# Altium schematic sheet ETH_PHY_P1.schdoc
size 594 x 419 mm; Symbol: Drawing-Symbol_A4; @Project Name: FPGA_motors_V3_0_4; @Page Count: 1; @Update Date: 2025-12-23; @Create Date: 2025-12-23; @Schematic Name: ETH_PHY; @Page No: 1; @Page Name: P1; Company: EasyEDA.com; Version: V1.0; Page Size: A4; @Create Time: 13:22:03; @Update Time: 14:22:09; Border: 1; Width: 2338; Height: 1652; Region Start: 1; X Region Count: 6; Y Region Count: 4; Blade Width: 10; Title Block Position: 3; Device: Drawing-Symbol_A4
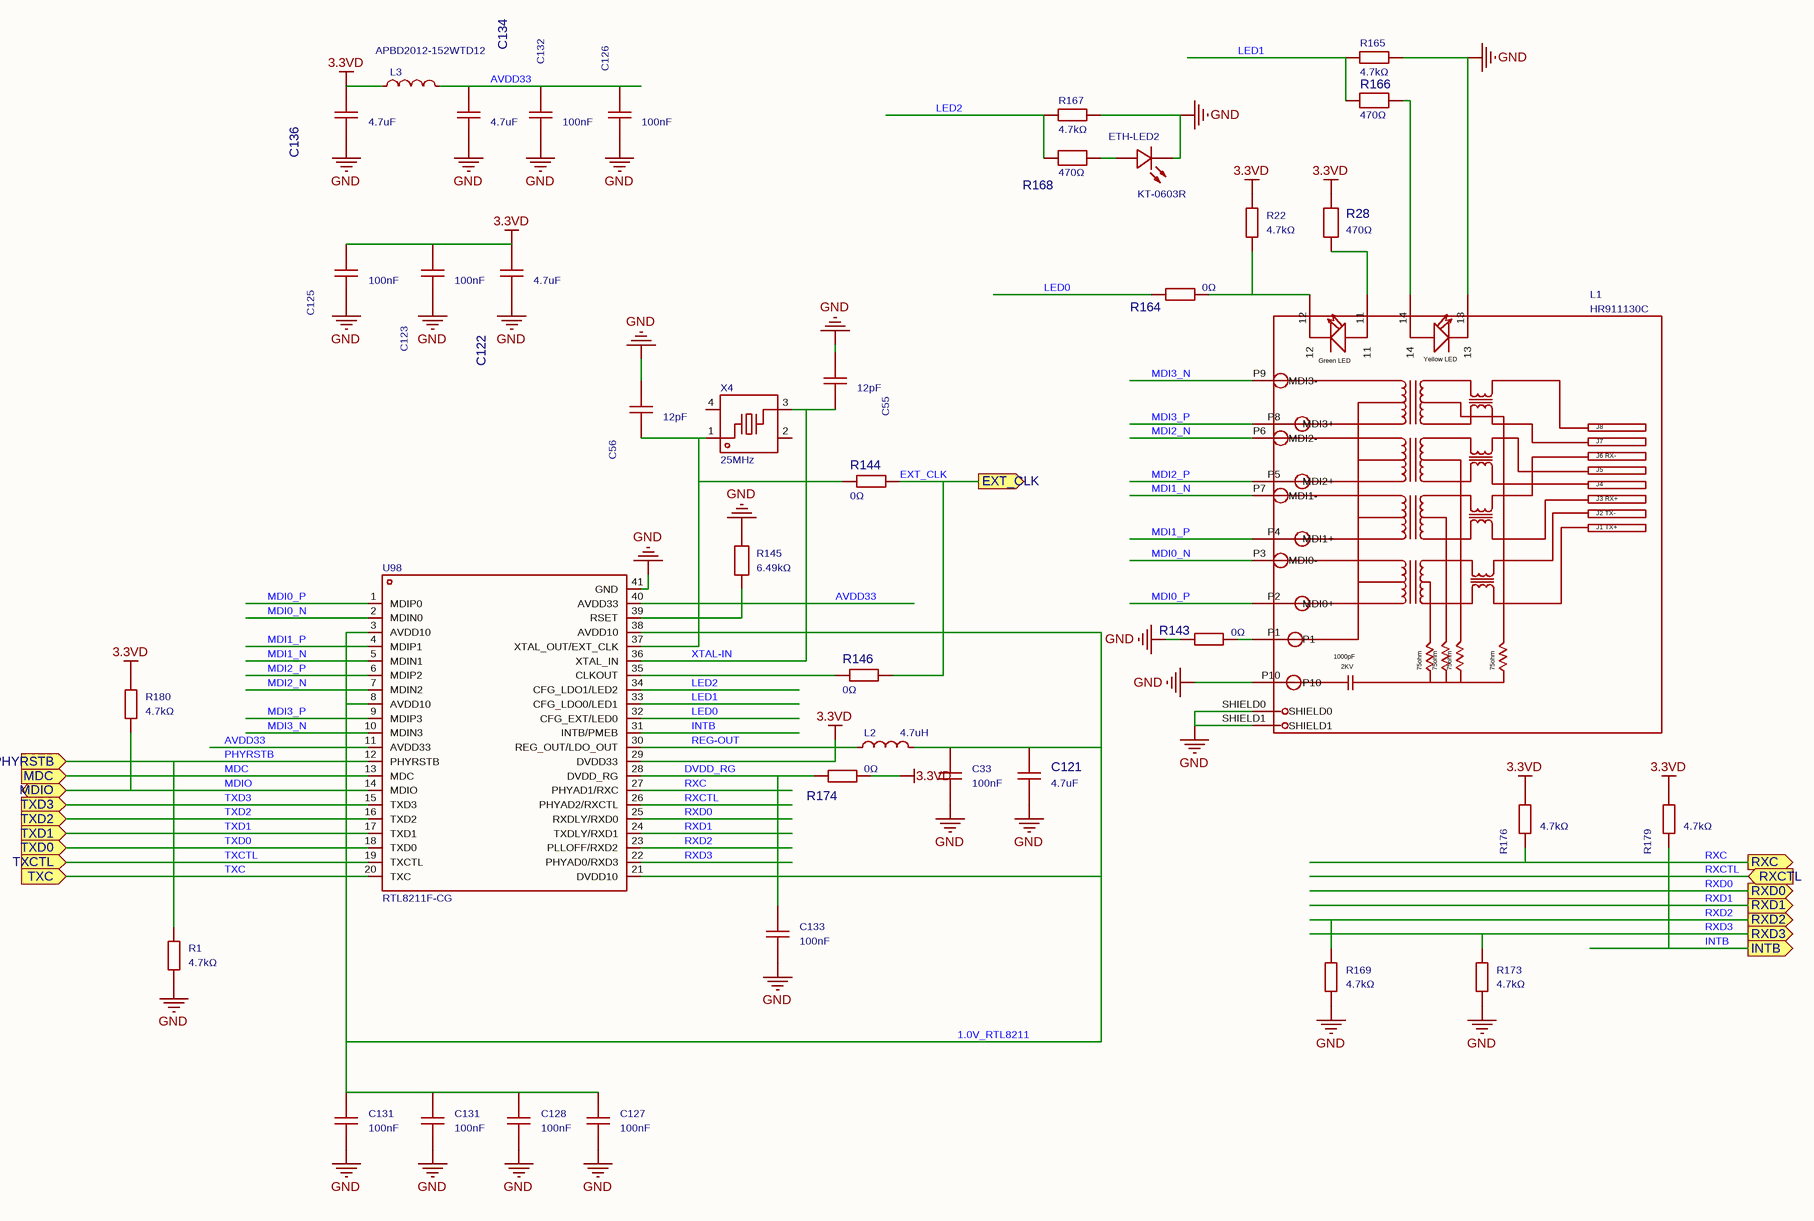
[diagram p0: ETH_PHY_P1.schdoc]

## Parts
(Parts that share a designator on the sheet are numbered #1, #2 ... from top to bottom, then left to right.)
C33  100nF  [C0402]
C55  12pF  [C0402]
C56  12pF  [C0402]
C121  4.7uF  [C0402]
C122  4.7uF  [C0402]
C123  100nF  [C0402]
C125  100nF  [C0402]
C126  100nF  [C0402]
C127  100nF  [C0402]
C128  100nF  [C0402]
C131#1  100nF  [C0402]
C131#2  100nF  [C0402]
C132  100nF  [C0402]
C133  100nF  [C0402]
C134  4.7uF  [C0402]
C136  4.7uF  [C0402]
ETH-LED2  KT-0603R  [LED0603-RD]
L1  HR911130C  [RJ45-TH_HR911130C]
L2  4.7uH  [IND-SMD_L7.8-W7.0_SUMIDA_CD73]
L3  APBD2012-152WTD12  [L0805]
R1  4.7kΩ  [R0402]
R22  4.7kΩ  [R0402]
R28  470Ω  [R0402]
R143  0Ω  [R0402]
R144  0Ω  [R0402]
R145  6.49kΩ  [R0402]
R146  0Ω  [R0402]
R164  0Ω  [R0402]
R165  4.7kΩ  [R0402]
R166  470Ω  [R0402]
R167  4.7kΩ  [R0402]
R168  470Ω  [R0402]
R169  4.7kΩ  [R0402]
R173  4.7kΩ  [R0402]
R174  0Ω  [R0402]
R176  4.7kΩ  [R0402]
R179  4.7kΩ  [R0402]
R180  4.7kΩ  [R0402]
U98  RTL8211F-CG  [WQFN-40_L5.0-W5.0-P0.4-BL-EP]
X4  25MHz  [CRYSTAL-SMD_4P-L5.0-W3.2-BL]

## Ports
EXT_CLK (out), INTB (out), MDC (in), MDIO (bidir), PHYRSTB (in), RXC (out), RXCTL (in), RXD0 (out), RXD1 (out), RXD2 (out), RXD3 (out), TXC (in), TXCTL (in), TXD0 (in), TXD1 (in), TXD2 (in), TXD3 (in)

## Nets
3.3VD: C122.1 C123.1 C125.1 C136.1 L3.1 R22.2 R28.2 R174.2 R176.1 R179.1 R180.1 U98.29(DVDD33)
GND: C33.2 C55.2 C56.2 C121.2 C122.2 C123.2 C125.2 C126.2 C127.2 C128.2 C131#1.2 C131#2.2 C132.2 C133.2 C134.2 C136.2 ETH-LED2.1(K) L1.13 L1.P10 L1.SHIELD0 L1.SHIELD1 R1.2 R143.1 R145.2 R165.1 R167.1 R169.2 R173.2 U98.41(GND)
1.0V_RTL8211: C33.1 C121.1 C127.1 C128.1 C131#1.1 C131#2.1 L2.2 U98.3(AVDD10) U98.8(AVDD10) U98.21(DVDD10) U98.38(AVDD10)
AVDD33: C126.1 C132.1 C134.1 L3.2 U98.11(AVDD33) U98.40(AVDD33)
DVDD_RG: C133.1 R174.1 U98.28(DVDD_RG)
EXT_CLK: R144.2 R146.2 ; port EXT_CLK
INTB: R179.2 U98.31(INTB/PMEB) ; port INTB
LED0: R164.1 U98.32(CFG_EXT/LED0)
LED1: R165.2 R166.2 U98.33(CFG_LDO0/LED1)
LED2: R167.2 R168.2 U98.34(CFG_LDO1/LED2)
MDC: U98.13(MDC) ; port MDC
MDI0_N: L1.P3(MDI0-) U98.2(MDIN0)
MDI0_P: L1.P2(MDI0+) U98.1(MDIP0)
MDI1_N: L1.P7(MDI1-) U98.5(MDIN1)
MDI1_P: L1.P4(MDI1+) U98.4(MDIP1)
MDI2_N: L1.P6(MDI2-) U98.7(MDIN2)
MDI2_P: L1.P5(MDI2+) U98.6(MDIP2)
MDI3_N: L1.P9(MDI3-) U98.10(MDIN3)
MDI3_P: L1.P8(MDI3+) U98.9(MDIP3)
MDIO: R180.2 U98.14(MDIO) ; port MDIO
PHYRSTB: R1.1 U98.12(PHYRSTB) ; port PHYRSTB
REG-OUT: L2.1 U98.30(REG_OUT/LDO_OUT)
RXC: R176.2 U98.27(PHYAD1/RXC) ; port RXC
RXCTL: U98.26(PHYAD2/RXCTL) ; port RXCTL
RXD0: U98.25(RXDLY/RXD0) ; port RXD0
RXD1: U98.24(TXDLY/RXD1) ; port RXD1
RXD2: R169.1 U98.23(PLLOFF/RXD2) ; port RXD2
RXD3: R173.1 U98.22(PHYAD0/RXD3) ; port RXD3
TXC: U98.20(TXC) ; port TXC
TXCTL: U98.19(TXCTL) ; port TXCTL
TXD0: U98.18(TXD0) ; port TXD0
TXD1: U98.17(TXD1) ; port TXD1
TXD2: U98.16(TXD2) ; port TXD2
TXD3: U98.15(TXD3) ; port TXD3
XTAL-IN: C55.1 U98.36(XTAL_IN) X4.3
NetC56_1: C56.1 R144.1 U98.37(XTAL_OUT/EXT_CLK) X4.1
NetETH-LED2_2: ETH-LED2.2(A) R168.1
NetL1_11: L1.11 R28.1
NetL1_12: L1.12 R22.1 R164.2
NetL1_14: L1.14 R166.1
NetL1_P1: L1.P1 R143.2
NetR145_1: R145.1 U98.39(RSET)
NetR146_1: R146.1 U98.35(CLKOUT)

Not connected (* = marked no-connect by the designer): X4 2(GND) 4(GND)

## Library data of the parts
C33 C123 C125-C128 C131#1 C131#2 C132 C133 = CL05B104KB54PNC: Capacitance: Tolerance:±10% Tolerance:±10% Voltage Rated: Temperature Coefficient:; Manufacturer: SAMSUNG(三星); Check: true; AddInBom: yes; ModelId: b7d13df3e9464d7a99d0651d1a5b4d57; ModelName: C0402_L1.0-W0.5-H0.5; ModelTransform: 39.37,19.685,0,0,0,0,0,0,0; Tolerance: ±10%
C55 C56 = V120J0402HQC500NBT: Capacitance:12pF Voltage Rating:50V Temperature Coefficient:C0G; Manufacturer: VIIYONG(微容); Check: true; AddInBom: yes; ModelId: b7d13df3e9464d7a99d0651d1a5b4d57; ModelName: C0402_L1.0-W0.5-H0.5; ModelTransform: 39.37,19.685,0,0,0,0,0,0,0; Voltage Rating: 50V; Temperature Coefficient: C0G
C121 C122 C134 C136 = LMK105BBJ475MVLF: Capacitance: Tolerance:±20% Tolerance:±20% Voltage Rated: Temperature Coefficient:; Manufacturer: TAIYO YUDEN(太诱); Check: true; AddInBom: yes; ModelId: b7d13df3e9464d7a99d0651d1a5b4d57; ModelName: C0402_L1.0-W0.5-H0.5; ModelTransform: 39.37,19.685,0,0,0,0,0,0,0; Tolerance: ±20%
ETH-LED2 = KT-0603R: Emitted Color:Red Power Dissipation:- Forward Current:- Dominant Wavelength:- Dominant Wavelength:- Peak Wavelength:- Diode Configuration:- Lens Color:- Color Temperature:- Color Temperature:- Viewing Angle:- Mounting Sytle:- Operating Temperature:-40℃~+8; Manufacturer: KENTO; AddInBom: yes; ModelId: 5e3b568068dd46cf8019c1d1baa0031b; ModelTransform: 63.7794,32.283,0,0,0,0,0,0,0; Emitted Color: Red
L1 = HR911130C: Connector Type:RJ45 Jack Mounting Type:Right Angle Number of Ports:1 LED:With LED Shielding:Shielded Ratings:- Operating Temperature:- Operating Temperature:-; Manufacturer: HANRUN(汉仁); AddInBom: yes; ModelId: e78ef41ce2b340c38ac329b1488052a9; ModelTransform: 716.118,838.62,0,180,0,0,0,86.614,-157.48; Number of Ports: 1
L2 = FCD75-4R7M: Inductance:4.7uH Tolerance:±20% Tolerance:±20% Current - Saturation(Isat):4.2A DC Resistance(DCR):30mΩ Type:-; Manufacturer: cjiang(长江微电); AddInBom: yes; ModelId: 9e13d2225fae48e3b7232bd608f073d1; ModelTransform: 304.546,275.59,0,0,0,0,-0.005,0,0; Tolerance: ±20%; Current - Saturation(Isat): 4.2A; DC Resistance(DCR): 30mΩ
L3 = APBD2012-152WTD12: Impedance @ Frequency:1.5kΩ@100MHz Tolerance:±25% Tolerance:±25% DC Resistance(DCR):400mΩ Current Rating:550mA Operating Temperature:-55℃~+125℃ Operating Temperature:-55℃~+125℃; Manufacturer: APV(爱普微); AddInBom: yes; ModelId: b83c7c5430874b8eb2319a65d9433429; ModelName: R0805_L2.0-W1.3-H0.6; ModelTransform: 78.74,51.181,0,0,0,0,0,0.001,0; Tolerance: ±25%; DC Resistance(DCR): 400mΩ; Current Rating: 550mA
R1 = 0402WGF4701TCE: Type:Thick Film Resistors Resistance:4.7kΩ Tolerance:±1% Tolerance:±1% Power(Watts): Overload Voltage (Max): Temperature Coefficient:±100ppm/℃ Temperature Coefficient:±100ppm/℃ Operating Temperature Range:-55℃~+155℃ Operating Temperature Range:-55℃~+155℃; Manufacturer: UNI-ROYAL(厚声); Symbol: RT0402BRD074K7L; 3D Model: efdecb7dae4442949d28eecaf748420f0819f05c4eef4c71ace90d822a990e87; 3D Model Transform: 39.37,19.685,0,0,0,0,0,0,0; Tolerance: ±1%; Power(Watts): 62.5mW; Voltage-Supply(Max): 50V; AddInBom: yes; ModelName: R0402_L1.0-W0.5-H0.4
R22 R165 R167 R169 R179 R180 = 0402WGF4701TCE: Type:Thick Film Resistors Resistance:4.7kΩ Tolerance:±1% Tolerance:±1% Power(Watts): Overload Voltage (Max): Temperature Coefficient:±100ppm/℃ Temperature Coefficient:±100ppm/℃ Operating Temperature Range:-55℃~+155℃ Operating Temperature Range:-55℃~+155℃; Manufacturer: UNI-ROYAL(厚声); Symbol: RT0402BRD074K7L; AddInBom: yes; ModelId: efdecb7dae4442949d28eecaf748420f0819f05c4eef4c71ace90d822a990e87; ModelName: R0402_L1.0-W0.5-H0.4; ModelTransform: 39.37,19.685,0,0,0,0,0,0,0; Tolerance: ±1%; Power(Watts): 62.5mW; Voltage-Supply(Max): 50V
R28 R166 R168 = 0402WGF4700TCE: Type:Thick Film Resistors Resistance: Tolerance:±1% Tolerance:±1% Power(Watts): Overload Voltage (Max): Temperature Coefficient:±100ppm/℃ Temperature Coefficient:±100ppm/℃ Operating Temperature Range:-55℃~+155℃ Operating Temperature Range:-55℃~+155℃; Manufacturer: UNI-ROYAL(厚声); Symbol: ERJ2RKF4700X; AddInBom: yes; ModelId: efdecb7dae4442949d28eecaf748420f; ModelName: R0402_L1.0-W0.5-H0.4; ModelTransform: 39.37,19.685,0,0,0,0,0,0,0; Tolerance: ±1%
R143 = 0402WGF0000TCE: Type:Thick Film Resistor Resistance:0Ω Tolerance:±1% Tolerance:±1% Power(Watts):62.5mW Voltage-Supply(Max):50V Temperature Coefficient:±800ppm/℃ Temperature Coefficient:±800ppm/℃ Operating Temperature:-55℃~+155℃ Operating Temperature:-55℃~+155℃; Manufacturer: UNI-ROYAL(厚声); AddInBom: yes; ModelId: efdecb7dae4442949d28eecaf748420f; ModelName: R0402_L1.0-W0.5-H0.4; ModelTransform: 39.37,19.685,0,0,0,0,0,0,0; Tolerance: ±1%; Power(Watts): 62.5mW; Voltage-Supply(Max): 50V
R144 R146 = 0402WGF0000TCE: Type:Thick Film Resistor Resistance:0Ω Tolerance:±1% Tolerance:±1% Power(Watts):62.5mW Voltage-Supply(Max):50V Temperature Coefficient:±800ppm/℃ Temperature Coefficient:±800ppm/℃ Operating Temperature:-55℃~+155℃ Operating Temperature:-55℃~+155℃; Manufacturer: UNI-ROYAL(厚声); Add into BOM: no; ConvertToPcb: yes; ModelId: efdecb7dae4442949d28eecaf748420f; ModelName: R0402_L1.0-W0.5-H0.4; ModelTransform: 39.37,19.685,0,0,0,0,0,0,0; Tolerance: ±1%; Power(Watts): 62.5mW; Voltage-Supply(Max): 50V
R145 = RT0402BRE076K49L: Type:Thin Film Resistor Resistance: Tolerance:±0.1% Tolerance:±0.1% Power(Watts): Temperature Coefficient:±50ppm/℃ Temperature Coefficient:±50ppm/℃ Operating Temperature Range:-55℃~+155℃ Operating Temperature Range:-55℃~+155℃; Manufacturer: YAGEO(国巨); AddInBom: yes; ModelId: efdecb7dae4442949d28eecaf748420f; ModelName: R0402_L1.0-W0.5-H0.4; ModelTransform: 39.37,19.685,0,0,0,0,0,0,0; Tolerance: ±0.1%
R164 R174 = 0402WGF0000TCE: Type:Thick Film Resistor Resistance:0Ω Tolerance:±1% Tolerance:±1% Power(Watts):62.5mW Voltage-Supply(Max):50V Temperature Coefficient:±800ppm/℃ Temperature Coefficient:±800ppm/℃ Operating Temperature:-55℃~+155℃ Operating Temperature:-55℃~+155℃; Manufacturer: UNI-ROYAL(厚声); Add into BOM: yes; ModelId: efdecb7dae4442949d28eecaf748420f; ModelName: R0402_L1.0-W0.5-H0.4; ModelTransform: 39.37,19.685,0,0,0,0,0,0,0; Tolerance: ±1%; Power(Watts): 62.5mW; Voltage-Supply(Max): 50V
R173 R176 = 0402WGF4701TCE: Type:Thick Film Resistors Resistance:4.7kΩ Tolerance:±1% Tolerance:±1% Power(Watts): Overload Voltage (Max): Temperature Coefficient:±100ppm/℃ Temperature Coefficient:±100ppm/℃ Operating Temperature Range:-55℃~+155℃ Operating Temperature Range:-55℃~+155℃; Manufacturer: UNI-ROYAL(厚声); Add into BOM: no; Symbol: RT0402BRD074K7L; ConvertToPcb: yes; ModelId: efdecb7dae4442949d28eecaf748420f0819f05c4eef4c71ace90d822a990e87; ModelName: R0402_L1.0-W0.5-H0.4; ModelTransform: 39.37,19.685,0,0,0,0,0,0,0; Tolerance: ±1%; Power(Watts): 62.5mW; Voltage-Supply(Max): 50V
U98 = RTL8211F-CG: Applications Function:- Number of Channels:- MAC Interface:RGMII Voltage - Supply:1.8V；2.5V；3.3V；1.5V Voltage - Supply:1.8V；2.5V；3.3V；1.5V; Manufacturer: REALTEK(瑞昱); AddInBom: yes; ModelId: fb095453d1104b15914498f9c172c0c2; ModelTransform: 197.6374,197.6374,0,0,0,0,0,0,0; MAC Interface: RGMII
X4 = XC53M4-25.000-F12JJDT: Type:Surface Mount Crystal Frequency:25MHz Normal temperature Frequency Tolerance:±30ppm Normal temperature Frequency Tolerance:±30ppm Load Capacitance:12pF Frequency Stability:±30ppm Frequency Stability:±30ppm Equivalent Series Resistance(ESR):50Ω Operat; Manufacturer: HCI(杭晶); AddInBom: yes; ModelId: 701e1f32ae8c4344bf4037d0fc939a81; ModelTransform: 196.85,125.984,0,0,0,0,0,0,0; Normal temperature Frequency Tolerance: ±30ppm; Load Capacitance: 12pF; Equivalent Series Resistance(ESR): 50Ω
